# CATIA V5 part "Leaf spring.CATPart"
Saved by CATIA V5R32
Part number: Part1
Material "Steel": density 7860 kg/m3, Young's modulus 2e+11 Pa, Poisson ratio 0.266, thermal expansion 1.17e-05 1/K
Bounding box of the stored display mesh (mm): x 0 to 6, y -52.464 to 52.464, z -1 to 10.425
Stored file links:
  D:\PROJECTS\Project 2022\CATIA V5 6R 2022\Resources\Tutorial Files\c19_catia_v5_6r2022_tut\C19_tut_03.CATPart\Leaf spring.CATPart
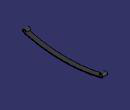
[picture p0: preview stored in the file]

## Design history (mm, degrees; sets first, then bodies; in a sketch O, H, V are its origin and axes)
Body1 (main body), material "Steel"
  Sketch1 on yz-plane, origin (0, 0, 0), H (0, 1, 0), V (0, 0, 1)
    arc A1 centre (0, 199) radius 199 from (-50.3797, 6.4828) to (50.3797, 6.4828) ccw
    point P1 (0, 199)
    arc A2 centre (0, 199) radius 200 from (-50.6329, 5.5154) to (50.6329, 5.5154) ccw
    arc A3 centre (-50, 7.9339) radius 2.5 from (-47.5, 7.9339) to (-50.6329, 5.5154) ccw
    point P2 (-50, 7.9339)
    arc A4 centre (50, 7.9339) radius 2.5 from (47.5, 7.9339) to (50.6329, 5.5154) cw
    arc A5 centre (-50, 7.9339) radius 1.5 from (-48.5, 7.9339) to (-50.3797, 6.4828) ccw
    point P4 (50, 7.9339)
    arc A6 centre (50, 7.9339) radius 1.5 from (48.5, 7.9339) to (50.3797, 6.4828) cw
    point P8 (50.3797, 6.4828)
    line L1 (48.5, 7.9339) -> (47.5, 7.9339)
    point P10 (-47.5, 7.9339)
    point P11 (50.3797, 6.4828)
    line L2 (-47.5, 7.9339) -> (-48.5, 7.9339)
    distance A1 A2 = 1
    distance P4 P2 = 100
    radius A3 = 2.5
    radius A2 = 200
    coincidence: A1 O, P1 V, A6 P8, L1 P10, A1 P11, L1 L2, L2 P2
    concentricity: A1 A2
    tangency: A3 A2, A5 A1
    symmetry: A3 A4 V, A5 A6 V
    horizontal: L1 H, L2 H
  Pad1: profile Sketch1, direction (1, 0, 0), length 6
